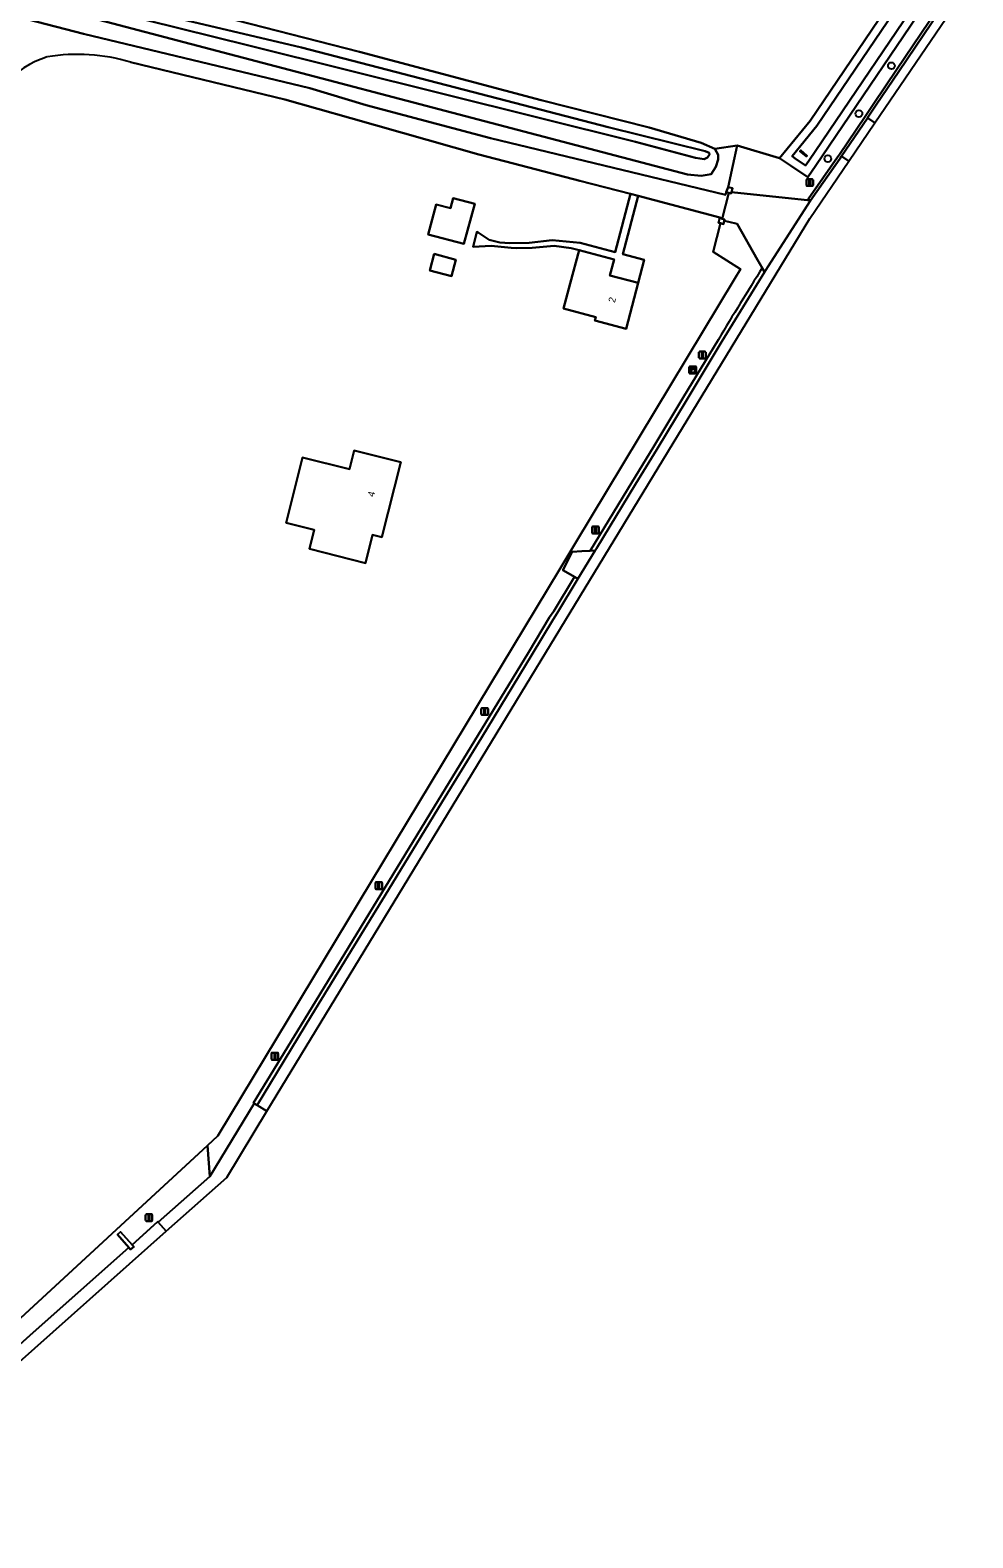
# Model space of a CAD drawing. Extents: x 156502 to 159075, y 384229 to 386100.
# Drawn here: x 158764.8 to 158901.4, y 384551 to 384769.6 of the extents above; entities that cross this region are included whole.
import ezdxf

# ---------------------------------------------------------------- set-up
doc = ezdxf.new("R2010")
doc.units = 0
for name, color, linetype in [('IMGEO_Boom', 7, 'Continuous'), ('IMGEO_Gemengd_bos', 7, 'Continuous'), ('IMGEO_Greppel_droge_sloot', 7, 'Continuous'), ('IMGEO_Groenvoorziening', 7, 'Continuous'), ('IMGEO_Hek', 7, 'Continuous'), ('IMGEO_Inrit_onverhard', 7, 'Continuous'), ('IMGEO_Kademuur', 7, 'Continuous'), ('IMGEO_Kast', 7, 'Continuous'), ('IMGEO_Lichtmast', 7, 'Continuous'), ('IMGEO_Muur', 7, 'Continuous'), ('IMGEO_Oever', 7, 'Continuous'), ('IMGEO_Pand', 7, 'Continuous'), ('IMGEO_Pand_nummerreeks', 7, 'Continuous'), ('IMGEO_Rijbaan_lokaal_gesloten', 7, 'Continuous'), ('IMGEO_Rijbaan_lokaal_halfverhard', 7, 'Continuous'), ('IMGEO_Rijbaan_lokaal_open', 7, 'Continuous'), ('IMGEO_Voetpad_open', 7, 'Continuous'), ('IMGEO_Waterloop', 7, 'Continuous')]:
    doc.layers.add(name, color=color, linetype=linetype)

msp = doc.modelspace()

# ---------------------------------------------------------------- linework, layer by layer
at = {"layer": 'IMGEO_Boom'}
for centre in [(158889.61, 384764.45), (158884.91, 384757.51), (158880.4, 384750.98)]:
    msp.add_circle(centre, 0.489, dxfattribs=at)
at = {"layer": 'IMGEO_Gemengd_bos'}
for points in [[(158784.83, 384773.55), (158812.52, 384766.45), (158838.88, 384759.47), (158854.51, 384755.51), (158862.04, 384753.27), (158864.05, 384752.43), (158867.27, 384752.87), (158873.42, 384751.07), (158877.84, 384756.47), (158893.69, 384779.91)], [(158733.14, 384554.95), (158790.51, 384607.91), (158792.03, 384609.32), (158841.61, 384691.58), (158843.78, 384695.17), (158866.94, 384733.59), (158867.77, 384734.97), (158863.79, 384737.47), (158864.83, 384741.62), (158864.56, 384741.69), (158864.76, 384742.46), (158852.92, 384745.57), (158850.7, 384737.14), (158853.8, 384736.32), (158852.92, 384732.98), (158851.17, 384726.33), (158846.66, 384727.5), (158846.78, 384728.02), (158842.12, 384729.26), (158843.07, 384732.88), (158844.35, 384737.71), (158843.23, 384738.01), (158840.75, 384738.36), (158837.58, 384738.05), (158835.32, 384737.99), (158834.54, 384738.05), (158831.63, 384738.34), (158829.03, 384738.2), (158829.54, 384740.38), (158829.73, 384740.28), (158831.34, 384739.22), (158832.88, 384738.82), (158834.34, 384738.74), (158837.12, 384738.76), (158840.46, 384739.16), (158844.5, 384738.77), (158849.61, 384737.42), (158851.83, 384745.86), (158844.48, 384747.79), (158835.95, 384750), (158829.81, 384751.59), (158811.28, 384756.83), (158801.73, 384759.55), (158779.36, 384764.96)]]:
    msp.add_lwpolyline(points, dxfattribs=at)
for points in [[(158823.67, 384744.35), (158825.73, 384743.79), (158826.13, 384745.27), (158829.24, 384744.43), (158827.67, 384738.61), (158822.5, 384740)], [(158823.35, 384737.16), (158826.52, 384736.33), (158825.89, 384733.95), (158822.73, 384734.79)], [(158801.9, 384698.18), (158804.29, 384707.68), (158811.07, 384705.96), (158811.75, 384708.67), (158818.54, 384706.96), (158815.8, 384696.1), (158814.44, 384696.43), (158813.42, 384692.36), (158805.28, 384694.44), (158805.97, 384697.15)]]:
    msp.add_lwpolyline(points, close=True, dxfattribs=at)
for centre, radius, start, end in [((158771.71, 384752.09), 14.35, 107.8735, 167.3223), ((158771.63, 384739.14), 26.96, 73.3305, 99.2275)]:
    msp.add_arc(centre, radius, start, end, dxfattribs=at)
at = {"layer": 'IMGEO_Greppel_droge_sloot'}
for points in [[(159031.35, 384974.88), (159040.49, 384988.15), (159045.57, 384995.54), (159044.46, 384996.27), (159030.98, 384976.59), (159029.33, 384974.32), (159012.57, 384950.07), (159000.98, 384934.13), (158984.01, 384911.86), (158954, 384866.95), (158894.7, 384779.23), (158878.82, 384755.73), (158875.22, 384751.33), (158875.67, 384751.01), (158877.18, 384749.98), (158877.66, 384750.69), (158896.26, 384778.17), (158984.63, 384908.74), (158998.99, 384929.12), (159015.05, 384952.44)], [(158877.42, 384751.41), (158877.3, 384751.28), (158876.35, 384752.09), (158876.47, 384752.22)]]:
    msp.add_lwpolyline(points, close=True, dxfattribs=at)
at = {"layer": 'IMGEO_Groenvoorziening'}
for points in [[(158710.97, 384785.08), (158772.53, 384769.1), (158805.34, 384761.18), (158813.52, 384758.75), (158831.51, 384753.95), (158847.93, 384750), (158865.57, 384745.76), (158865.67, 384746.13), (158865.95, 384746.85), (158866.64, 384750), (158867.27, 384752.87), (158864.05, 384752.43), (158864.49, 384751.52), (158864.52, 384750.84), (158864.19, 384749.8), (158863.48, 384748.74), (158862.05, 384748.48), (158860.05, 384748.69), (158766.32, 384773.34)], [(158897.27, 384777.48), (158878.67, 384750), (158877.51, 384748.28), (158874.98, 384750), (158873.42, 384751.07), (158867.27, 384752.87), (158866.64, 384750), (158865.95, 384746.85), (158866.59, 384746.68), (158866.47, 384746.25), (158866.45, 384746.14), (158877.88, 384744.9), (158877.56, 384745.13), (158881.81, 384751.2), (158882.07, 384751.58), (158885.8, 384757.08), (158887.08, 384759), (158890.33, 384763.86), (158896.3, 384772.65)], [(158870.9, 384735.15), (158870.22, 384736.33), (158867.26, 384741.51), (158866.04, 384741.8), (158865.39, 384741.95), (158865.27, 384741.5), (158864.83, 384741.62), (158863.79, 384737.47), (158867.77, 384734.97), (158866.94, 384733.59), (158843.78, 384695.17), (158841.61, 384691.58), (158792.03, 384609.32), (158790.51, 384607.91), (158790.87, 384603.43), (158797.27, 384614.03), (158797.19, 384614.08), (158805.08, 384627.05), (158812.71, 384639.55), (158815.69, 384644.4), (158820.92, 384652.97), (158824.01, 384658.04), (158829.7, 384667.34), (158837.01, 384679.38), (158840.07, 384684.5), (158840.68, 384685.4), (158843.67, 384690.35), (158842.78, 384690.88), (158842, 384691.33), (158843.36, 384693.99), (158844.76, 384694.06), (158845.95, 384694.12), (158852.03, 384704.12), (158855.11, 384709.13), (158859.46, 384716.35)], [(158859.46, 384716.35), (158864.55, 384724.77)], [(158758.39, 384574.66), (158765.24, 384580.8), (158771.71, 384586.55), (158779.13, 384593.12), (158777.49, 384595.03), (158777.92, 384595.4), (158779.58, 384593.53), (158783.29, 384596.87), (158783.37, 384596.78), (158790.87, 384603.43), (158790.51, 384607.91), (158733.14, 384554.95), (158670.56, 384500), (158573.19, 384414.32), (158574.92, 384411.58), (158576.2, 384412.29), (158589.14, 384392.31), (158589.02, 384389.56), (158587.72, 384389.57), (158587.8, 384389.16), (158584.38, 384386.89), (158585.91, 384384.8), (158507.39, 384332.46)]]:
    msp.add_lwpolyline(points, dxfattribs=at)
msp.add_arc((159457.14, 384368.86), 691.26, 148.0022, 149.01051, dxfattribs=at)
at = {"layer": 'IMGEO_Hek'}
for points in [[(158893.69, 384779.91), (158877.84, 384756.47), (158873.42, 384751.07)], [(158867.27, 384752.87), (158866.64, 384750)], [(158873.42, 384751.07), (158867.27, 384752.87)], [(158865.95, 384746.85), (158866.64, 384750)], [(158866.07, 384746.03), (158865.08, 384742.27)], [(158843.78, 384695.17), (158866.94, 384733.59), (158867.77, 384734.97), (158863.79, 384737.47), (158864.83, 384741.62)], [(158841.61, 384691.58), (158843.78, 384695.17)], [(158790.51, 384607.91), (158792.03, 384609.32), (158841.61, 384691.58)], [(158670.56, 384500), (158733.14, 384554.95), (158790.51, 384607.91)]]:
    msp.add_lwpolyline(points, dxfattribs=at)
at = {"layer": 'IMGEO_Inrit_onverhard'}
msp.add_lwpolyline([(158844.5, 384738.77), (158840.46, 384739.16), (158837.12, 384738.76), (158834.34, 384738.74), (158832.88, 384738.82), (158831.34, 384739.22), (158829.73, 384740.28), (158829.54, 384740.38), (158829.03, 384738.2), (158831.63, 384738.34), (158834.54, 384738.05), (158835.32, 384737.99), (158837.58, 384738.05), (158840.75, 384738.36), (158843.23, 384738.01), (158844.35, 384737.71), (158849.44, 384736.37), (158848.83, 384734.06), (158852.92, 384732.98), (158853.8, 384736.32), (158850.7, 384737.14), (158852.92, 384745.57), (158851.83, 384745.86), (158849.61, 384737.42)], close=True, dxfattribs=at)
at = {"layer": 'IMGEO_Kademuur'}
msp.add_lwpolyline([(158876.35, 384752.09), (158877.3, 384751.28), (158877.42, 384751.41), (158876.47, 384752.22)], close=True, dxfattribs=at)
at = {"layer": 'IMGEO_Kast'}
for p, q in [((158860.33, 384719.93), (158860.33, 384720.77)), ((158860.33, 384720.77), (158860.33, 384719.93)), ((158860.4, 384720.85), (158861.24, 384720.85)), ((158861.24, 384720.85), (158860.4, 384720.85)), ((158861.32, 384720.78), (158861.32, 384719.94)), ((158861.32, 384719.94), (158861.32, 384720.78)), ((158861.25, 384719.85), (158860.41, 384719.85)), ((158860.41, 384719.85), (158861.25, 384719.85))]:
    msp.add_line(p, q, dxfattribs=at)
for points in [[(158860.52, 384720.64), (158861.12, 384720.64), (158861.12, 384720.56), (158860.52, 384720.56), (158860.52, 384720.64)], [(158860.52, 384720.47), (158861.12, 384720.47), (158861.12, 384719.98), (158860.52, 384719.98), (158860.52, 384720.47)]]:
    msp.add_lwpolyline(points, dxfattribs=at)
msp.add_circle((158860.6, 384720.32), 0.0377, dxfattribs=at)
for centre, start, end in [((158860.4, 384720.78), 92.4484, 184.2845), ((158860.4, 384720.78), 92.4484, 184.2845), ((158861.25, 384720.78), 2.4484, 94.2845), ((158861.25, 384720.78), 2.4484, 94.2845), ((158860.4, 384719.93), 182.4484, 274.2845), ((158860.4, 384719.93), 182.4484, 274.2845), ((158861.25, 384719.93), 272.4484, 4.2845), ((158861.25, 384719.93), 272.4484, 4.2845)]:
    msp.add_arc(centre, 0.0779, start, end, dxfattribs=at)
at = {"layer": 'IMGEO_Lichtmast'}
for p, q in [((158877.3, 384747.12), (158877.3, 384747.91)), ((158877.3, 384747.91), (158877.3, 384747.12)), ((158877.4, 384748.01), (158878.18, 384748.01)), ((158878.18, 384748.01), (158877.4, 384748.01)), ((158878.18, 384747.02), (158877.4, 384747.02)), ((158877.4, 384747.02), (158878.18, 384747.02)), ((158878.28, 384747.91), (158878.28, 384747.12)), ((158878.28, 384747.12), (158878.28, 384747.91)), ((158861.73, 384722.11), (158861.73, 384722.91)), ((158861.73, 384722.91), (158861.73, 384722.11)), ((158861.83, 384723.01), (158862.62, 384723.01)), ((158862.62, 384723.01), (158861.83, 384723.01)), ((158862.72, 384722.91), (158862.72, 384722.11)), ((158862.72, 384722.11), (158862.72, 384722.91)), ((158862.62, 384722.01), (158861.83, 384722.01)), ((158861.83, 384722.01), (158862.62, 384722.01)), ((158846.24, 384696.74), (158846.24, 384697.54)), ((158846.24, 384697.54), (158846.24, 384696.74)), ((158846.34, 384697.64), (158847.13, 384697.64)), ((158847.13, 384697.64), (158846.34, 384697.64)), ((158847.13, 384696.64), (158846.34, 384696.64)), ((158846.34, 384696.64), (158847.13, 384696.64)), ((158847.23, 384697.54), (158847.23, 384696.74)), ((158847.23, 384696.74), (158847.23, 384697.54)), ((158830.17, 384670.43), (158830.17, 384671.23)), ((158830.17, 384671.23), (158830.17, 384670.43)), ((158830.27, 384671.33), (158831.06, 384671.33)), ((158831.06, 384671.33), (158830.27, 384671.33)), ((158831.06, 384670.33), (158830.27, 384670.33)), ((158830.27, 384670.33), (158831.06, 384670.33)), ((158831.16, 384671.23), (158831.16, 384670.43)), ((158831.16, 384670.43), (158831.16, 384671.23)), ((158814.84, 384645.19), (158814.84, 384645.99)), ((158814.84, 384645.99), (158814.84, 384645.19)), ((158814.94, 384646.09), (158815.73, 384646.09)), ((158815.73, 384646.09), (158814.94, 384646.09)), ((158815.83, 384645.99), (158815.83, 384645.19)), ((158815.83, 384645.19), (158815.83, 384645.99)), ((158815.73, 384645.09), (158814.94, 384645.09)), ((158814.94, 384645.09), (158815.73, 384645.09)), ((158799.78, 384620.46), (158799.78, 384621.26)), ((158799.78, 384621.26), (158799.78, 384620.46)), ((158799.88, 384621.36), (158800.67, 384621.36)), ((158800.67, 384621.36), (158799.88, 384621.36)), ((158800.67, 384620.36), (158799.88, 384620.36)), ((158799.88, 384620.36), (158800.67, 384620.36)), ((158800.77, 384621.26), (158800.77, 384620.46)), ((158800.77, 384620.46), (158800.77, 384621.26)), ((158781.63, 384597.96), (158782.42, 384597.96)), ((158782.42, 384597.96), (158781.63, 384597.96)), ((158781.53, 384597.06), (158781.53, 384597.86)), ((158781.53, 384597.86), (158781.53, 384597.06)), ((158782.42, 384596.96), (158781.63, 384596.96)), ((158781.63, 384596.96), (158782.42, 384596.96)), ((158782.52, 384597.86), (158782.52, 384597.06)), ((158782.52, 384597.06), (158782.52, 384597.86))]:
    msp.add_line(p, q, dxfattribs=at)
for points in [[(158877.71, 384747.89), (158877.87, 384747.89), (158877.87, 384747.14), (158877.71, 384747.14), (158877.71, 384747.89)], [(158862.15, 384722.89), (158862.3, 384722.89), (158862.3, 384722.14), (158862.15, 384722.14), (158862.15, 384722.89)], [(158846.66, 384697.52), (158846.81, 384697.52), (158846.81, 384696.77), (158846.66, 384696.77), (158846.66, 384697.52)], [(158830.59, 384671.2), (158830.74, 384671.2), (158830.74, 384670.45), (158830.59, 384670.45), (158830.59, 384671.2)], [(158815.26, 384645.97), (158815.41, 384645.97), (158815.41, 384645.22), (158815.26, 384645.22), (158815.26, 384645.97)], [(158800.2, 384621.24), (158800.35, 384621.24), (158800.35, 384620.49), (158800.2, 384620.49), (158800.2, 384621.24)], [(158781.95, 384597.84), (158782.1, 384597.84), (158782.1, 384597.09), (158781.95, 384597.09), (158781.95, 384597.84)]]:
    msp.add_lwpolyline(points, dxfattribs=at)
for centre, start, end in [((158877.4, 384747.91), 90, 180), ((158877.4, 384747.91), 90, 180), ((158877.4, 384747.12), 180, 270), ((158877.4, 384747.12), 180, 270), ((158878.18, 384747.91), 0, 90), ((158878.18, 384747.91), 360, 90), ((158878.18, 384747.12), 270, 0), ((158878.18, 384747.12), 270, 0), ((158861.83, 384722.91), 90, 180), ((158861.83, 384722.91), 90, 180), ((158862.62, 384722.91), 0, 90), ((158862.62, 384722.91), 360, 90), ((158861.83, 384722.11), 180, 270), ((158861.83, 384722.11), 180, 270), ((158862.62, 384722.11), 270, 0), ((158862.62, 384722.11), 270, 0), ((158846.34, 384697.54), 90, 180), ((158846.34, 384697.54), 90, 180), ((158846.34, 384696.74), 180, 270), ((158846.34, 384696.74), 180, 270), ((158847.13, 384697.54), 0, 90), ((158847.13, 384697.54), 360, 90), ((158847.13, 384696.74), 270, 0), ((158847.13, 384696.74), 270, 0), ((158830.27, 384671.23), 90, 180), ((158830.27, 384671.23), 90, 180), ((158830.27, 384670.43), 180, 270), ((158830.27, 384670.43), 180, 270), ((158831.06, 384671.23), 0, 90), ((158831.06, 384671.23), 360, 90), ((158831.06, 384670.43), 270, 0), ((158831.06, 384670.43), 270, 0), ((158814.94, 384645.99), 90, 180), ((158814.94, 384645.99), 90, 180), ((158815.73, 384645.99), 0, 90), ((158815.73, 384645.99), 360, 90), ((158814.94, 384645.19), 180, 270), ((158814.94, 384645.19), 180, 270), ((158815.73, 384645.19), 270, 0), ((158815.73, 384645.19), 270, 0), ((158799.88, 384621.26), 90, 180), ((158799.88, 384621.26), 90, 180), ((158799.88, 384620.46), 180, 270), ((158799.88, 384620.46), 180, 270), ((158800.67, 384621.26), 0, 90), ((158800.67, 384621.26), 360, 90), ((158800.67, 384620.46), 270, 0), ((158800.67, 384620.46), 270, 0), ((158781.63, 384597.86), 90, 180), ((158781.63, 384597.86), 90, 180), ((158782.42, 384597.86), 0, 90), ((158782.42, 384597.86), 360, 90), ((158781.63, 384597.06), 180, 270), ((158781.63, 384597.06), 180, 270), ((158782.42, 384597.06), 270, 0), ((158782.42, 384597.06), 270, 0)]:
    msp.add_arc(centre, 0.1, start, end, dxfattribs=at)
at = {"layer": 'IMGEO_Muur'}
for points in [[(158866.59, 384746.68), (158865.95, 384746.85), (158865.67, 384746.13), (158866.07, 384746.03), (158866.39, 384745.94), (158866.41, 384746), (158866.45, 384746.14), (158866.47, 384746.25)], [(158865.39, 384741.95), (158865.45, 384742.18), (158865.08, 384742.27), (158864.76, 384742.46), (158864.56, 384741.69), (158864.83, 384741.62), (158865.27, 384741.5)], [(158777.92, 384595.4), (158777.49, 384595.03), (158779.13, 384593.12), (158779.37, 384592.84), (158779.85, 384593.23), (158779.58, 384593.53)]]:
    msp.add_lwpolyline(points, close=True, dxfattribs=at)
at = {"layer": 'IMGEO_Oever'}
for points in [[(158897.27, 384777.48), (158985.64, 384908.04), (159000, 384928.41), (159040.92, 384987.85), (159046.32, 384995.68), (159044.95, 384996.49), (159043.4, 384997.4), (159042.89, 384997.7), (159030.55, 384976.89), (159000, 384934.86), (158983.01, 384912.57), (158952.98, 384867.63), (158893.69, 384779.91), (158877.84, 384756.47), (158873.42, 384751.07), (158874.98, 384750), (158877.51, 384748.28), (158878.67, 384750)], [(159031.35, 384974.88), (159015.05, 384952.44), (158998.99, 384929.12), (158984.63, 384908.74), (158896.26, 384778.17), (158877.66, 384750.69), (158877.18, 384749.98), (158875.67, 384751.01), (158875.22, 384751.33), (158878.82, 384755.73), (158894.7, 384779.23), (158954, 384866.95), (158984.01, 384911.86), (159000.98, 384934.13), (159012.57, 384950.07), (159029.33, 384974.32), (159030.98, 384976.59), (159044.46, 384996.27), (159045.57, 384995.54), (159040.49, 384988.15)], [(158864.05, 384752.43), (158862.04, 384753.27), (158854.51, 384755.51), (158838.88, 384759.47), (158812.52, 384766.45), (158784.83, 384773.55), (158771.92, 384776.7), (158768.34, 384777.21), (158766.8, 384777.13), (158765.62, 384776.92), (158765.09, 384775.83), (158764.9, 384774.83), (158765.02, 384773.91), (158766.32, 384773.34), (158860.05, 384748.69), (158862.05, 384748.48), (158863.48, 384748.74), (158864.19, 384749.8), (158864.52, 384750.84), (158864.49, 384751.52)], [(158852.55, 384753.42), (158796.49, 384767.39), (158766.65, 384774.82), (158766.98, 384775.89), (158804.12, 384767.1), (158848.58, 384755.57), (158862.64, 384752.06), (158863.23, 384751.85), (158863.25, 384751.59), (158862.95, 384751.14), (158862.49, 384750.9), (158861.24, 384751.12)]]:
    msp.add_lwpolyline(points, close=True, dxfattribs=at)
at = {"layer": 'IMGEO_Pand'}
for points in [[(158827.67, 384738.61), (158829.24, 384744.43), (158826.13, 384745.27), (158825.73, 384743.79), (158823.67, 384744.35), (158822.5, 384740)], [(158823.35, 384737.16), (158822.73, 384734.79), (158825.89, 384733.95), (158826.52, 384736.33)], [(158846.66, 384727.5), (158851.17, 384726.33), (158852.92, 384732.98), (158848.83, 384734.06), (158849.44, 384736.37), (158844.35, 384737.71), (158843.07, 384732.88), (158842.12, 384729.26), (158846.78, 384728.02)], [(158813.42, 384692.36), (158814.44, 384696.43), (158815.8, 384696.1), (158818.54, 384706.96), (158811.75, 384708.67), (158811.07, 384705.96), (158804.29, 384707.68), (158801.9, 384698.18), (158805.97, 384697.15), (158805.28, 384694.44)]]:
    msp.add_lwpolyline(points, close=True, dxfattribs=at)
at = {"layer": 'IMGEO_Rijbaan_lokaal_gesloten'}
for points in [[(158887.22, 384756.16), (159014.22, 384942.69), (159025.62, 384945.88), (159026.12, 384946.13), (159028.75, 384947.33), (159027.1, 384950.63), (159023.39, 384949.13)], [(158779.36, 384764.96), (158801.73, 384759.55), (158811.28, 384756.83), (158829.81, 384751.59), (158835.95, 384750), (158844.48, 384747.79), (158851.83, 384745.86), (158852.92, 384745.57), (158864.76, 384742.46), (158865.08, 384742.27), (158866.07, 384746.03), (158865.67, 384746.13), (158865.57, 384745.76), (158847.93, 384750), (158831.51, 384753.95), (158813.52, 384758.75), (158805.34, 384761.18), (158772.53, 384769.1), (158710.97, 384785.08)], [(158896.63, 384772.42), (158890.67, 384763.64), (158887.41, 384758.78), (158886.16, 384756.89), (158887.22, 384756.16)], [(158799.13, 384612.89), (158877.79, 384742.31), (158883.45, 384750.63), (158882.39, 384751.35), (158882.14, 384750.98), (158877.88, 384744.9), (158871.72, 384735.32), (158871.24, 384734.55), (158865.05, 384724.46), (158859.98, 384716.04), (158855.62, 384708.82), (158852.54, 384703.81), (158846.87, 384694.48), (158846.68, 384694.16), (158844.19, 384690.05), (158841.18, 384685.08), (158840.58, 384684.18), (158837.52, 384679.07), (158830.21, 384667.03), (158824.52, 384657.72), (158821.43, 384652.66), (158816.2, 384644.09), (158813.22, 384639.24), (158805.6, 384626.74), (158797.7, 384613.77), (158799.13, 384612.89)], [(158663.7, 384487.82), (158784.52, 384595.48), (158783.37, 384596.78), (158783.29, 384596.87), (158779.58, 384593.53), (158779.85, 384593.23), (158779.37, 384592.84), (158779.13, 384593.12), (158771.71, 384586.55), (158765.24, 384580.8), (158758.39, 384574.66), (158751.39, 384568.37), (158744.99, 384562.66), (158738.3, 384556.69), (158731.68, 384550.76)]]:
    msp.add_lwpolyline(points, dxfattribs=at)
msp.add_lwpolyline([(158883.45, 384750.63), (158887.22, 384756.16), (158886.16, 384756.89), (158886.14, 384756.85), (158882.4, 384751.35), (158882.39, 384751.35)], close=True, dxfattribs=at)
for centre, radius, start, end in [((158771.71, 384752.09), 14.35, 107.8735, 167.3223), ((158771.63, 384739.14), 26.96, 73.3305, 99.2275)]:
    msp.add_arc(centre, radius, start, end, dxfattribs=at)
at = {"layer": 'IMGEO_Rijbaan_lokaal_halfverhard'}
for points in [[(158896.3, 384772.65), (158890.33, 384763.86), (158887.08, 384759), (158885.8, 384757.08), (158882.07, 384751.58), (158881.81, 384751.2), (158877.56, 384745.13), (158877.88, 384744.9), (158882.14, 384750.98), (158882.39, 384751.35), (158882.4, 384751.35), (158886.14, 384756.85), (158886.16, 384756.89), (158887.41, 384758.78), (158890.67, 384763.64), (158896.63, 384772.42)], [(158865.05, 384724.46), (158871.24, 384734.55), (158870.9, 384735.15)], [(158864.55, 384724.77), (158859.46, 384716.35), (158855.11, 384709.13), (158852.03, 384704.12), (158845.95, 384694.12), (158846.68, 384694.16), (158846.87, 384694.48), (158852.54, 384703.81), (158855.62, 384708.82), (158859.98, 384716.04), (158865.05, 384724.46)]]:
    msp.add_lwpolyline(points, dxfattribs=at)
msp.add_lwpolyline([(158844.19, 384690.05), (158843.67, 384690.35), (158840.68, 384685.4), (158840.07, 384684.5), (158837.01, 384679.38), (158829.7, 384667.34), (158824.01, 384658.04), (158820.92, 384652.97), (158815.69, 384644.4), (158812.71, 384639.55), (158805.08, 384627.05), (158797.19, 384614.08), (158797.27, 384614.03), (158797.7, 384613.77), (158805.6, 384626.74), (158813.22, 384639.24), (158816.2, 384644.09), (158821.43, 384652.66), (158824.52, 384657.72), (158830.21, 384667.03), (158837.52, 384679.07), (158840.58, 384684.18), (158841.18, 384685.08)], close=True, dxfattribs=at)
msp.add_arc((159457.14, 384368.86), 691.26, 148.0022, 149.01051, dxfattribs=at)
at = {"layer": 'IMGEO_Rijbaan_lokaal_open'}
msp.add_lwpolyline([(158877.88, 384744.9), (158866.45, 384746.14), (158866.41, 384746), (158866.39, 384745.94), (158866.07, 384746.03), (158865.08, 384742.27), (158865.45, 384742.18), (158865.39, 384741.95), (158866.04, 384741.8), (158867.26, 384741.51), (158870.22, 384736.33), (158870.9, 384735.15), (158871.24, 384734.55), (158871.72, 384735.32)], close=True, dxfattribs=at)
msp.add_lwpolyline([(158799.13, 384612.89), (158797.7, 384613.77), (158797.27, 384614.03), (158790.87, 384603.43), (158783.37, 384596.78), (158784.52, 384595.48), (158793.3, 384603.3), (158799.13, 384612.89)], dxfattribs=at)
at = {"layer": 'IMGEO_Voetpad_open'}
msp.add_lwpolyline([(158846.68, 384694.16), (158845.95, 384694.12), (158844.76, 384694.06), (158843.36, 384693.99), (158842, 384691.33), (158842.78, 384690.88), (158843.67, 384690.35), (158844.19, 384690.05)], close=True, dxfattribs=at)
at = {"layer": 'IMGEO_Waterloop'}
msp.add_lwpolyline([(158766.65, 384774.82), (158796.49, 384767.39), (158852.55, 384753.42), (158861.24, 384751.12), (158862.49, 384750.9), (158862.95, 384751.14), (158863.25, 384751.59), (158863.23, 384751.85), (158862.64, 384752.06), (158848.58, 384755.57), (158804.12, 384767.1), (158766.98, 384775.89)], close=True, dxfattribs=at)

# ---------------------------------------------------------------- texts
at = {"layer": 'IMGEO_Pand_nummerreeks'}
for s, rotation, p in [('2', 75.2216, (158849.54, 384730.03)), ('4', 75.8317, (158814.64, 384701.88))]:
    msp.add_text(s, height=1, rotation=rotation, dxfattribs=at).set_placement(p)

doc.saveas('drawing.dxf')
